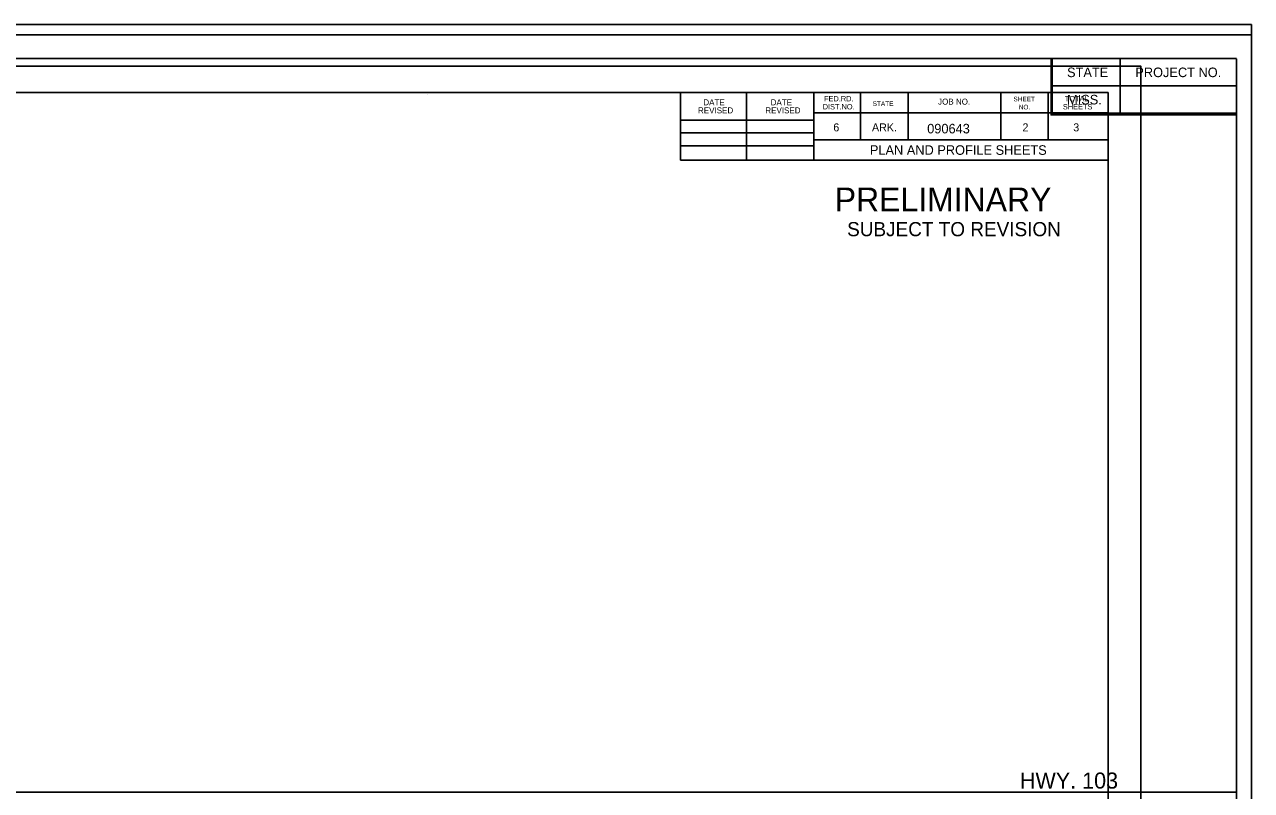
# Model space of a CAD drawing. Extents: x 1383694 to 1386843, y 1973227 to 1975727.
# Drawn here: x 1385944 to 1386843, y 1974979 to 1975540 of the extents above; entities that cross this region are included whole.
import ezdxf

# ---------------------------------------------------------------- set-up
doc = ezdxf.new("R2010")
doc.units = 0
for name, color, linetype in [('R_Border', 7, 'Continuous'), ('R_Border Prem', 7, 'Continuous'), ('R_No Plot', 7, 'Continuous'), ('SHEET_BORDER', 7, 'Continuous'), ('SHEET_BORDER_TX', 7, 'Continuous'), ('SHEET_PLOTTING_SHAPE', 7, 'Continuous')]:
    doc.layers.add(name, color=color, linetype=linetype)

msp = doc.modelspace()

# ---------------------------------------------------------------- linework, layer by layer
at = {"layer": 'R_Border'}
for p, q in [((1385156.93, 1975490.04), (1386737.83, 1975490.04)), ((1386239.07, 1975488.74), (1386239.07, 1975488.74)), ((1386239.07, 1975488.74), (1386239.07, 1975488.74)), ((1386424.63, 1975440.64), (1386424.63, 1975490.04)), ((1386473.03, 1975440.64), (1386473.03, 1975490.04)), ((1386522.33, 1975490.04), (1386522.33, 1975440.64)), ((1386556.53, 1975490.04), (1386556.53, 1975455.34)), ((1386591.23, 1975490.04), (1386591.23, 1975455.34)), ((1386659.13, 1975490.04), (1386659.13, 1975455.34)), ((1386693.83, 1975490.04), (1386693.83, 1975455.34)), ((1386737.83, 1974462.74), (1386737.83, 1975490.04)), ((1386737.83, 1975475.34), (1386522.33, 1975475.34)), ((1386424.63, 1975469.94), (1386522.33, 1975469.94)), ((1386424.63, 1975460.64), (1386522.33, 1975460.64)), ((1386737.83, 1975455.34), (1386522.33, 1975455.34)), ((1386537.13, 1975455.34), (1386737.83, 1975455.34)), ((1386424.63, 1975450.94), (1386522.33, 1975450.94)), ((1386737.83, 1975440.64), (1386424.63, 1975440.64))]:
    msp.add_line(p, q, dxfattribs=at)
at = {"layer": 'R_No Plot'}
msp.add_line((1385094.96, 1975509.53), (1386761.63, 1975509.53), dxfattribs=at)
msp.add_lwpolyline([(1385094.93, 1975509.53), (1386761.63, 1975509.53), (1386761.63, 1974442.85), (1385094.93, 1974442.85)], close=True, dxfattribs=at)
at = {"layer": 'SHEET_BORDER'}
for p, q in [((1386842.73, 1975539.94), (1386842.73, 1975539.94)), ((1385082.73, 1975532.44), (1386842.73, 1975532.44)), ((1385156.73, 1975514.94), (1386831.73, 1975514.94)), ((1386831.73, 1975514.89), (1386831.73, 1974464.94))]:
    msp.add_line(p, q, dxfattribs=at)
msp.add_lwpolyline([(1385156.73, 1975514.94), (1385156.73, 1974977.44), (1386831.73, 1974977.44), (1386831.73, 1975473.74), (1386695.93, 1975473.74), (1386695.93, 1975514.94)], close=True, dxfattribs=at)
at = {"layer": 'SHEET_BORDER_TX'}
for p, q in [((1386696.68, 1975514.89), (1386696.68, 1975474.89)), ((1386746.68, 1975514.89), (1386746.68, 1975474.89)), ((1386831.68, 1975494.89), (1386696.68, 1975494.89)), ((1386696.68, 1975474.89), (1386831.68, 1975474.89))]:
    msp.add_line(p, q, dxfattribs=at)
at = {"layer": 'SHEET_PLOTTING_SHAPE'}
msp.add_lwpolyline([(1385112.73, 1974439.94), (1386842.73, 1974439.94), (1386842.73, 1975539.94), (1385112.73, 1975539.94)], close=True, dxfattribs=at)

# ---------------------------------------------------------------- texts
at = {"layer": 'R_Border'}
for s, height, p in [('DATE', 4.396, (1386441.32, 1975480.72)), ('DATE', 4.396, (1386490.62, 1975480.72)), ('DIST.NO.', 3.91, (1386528.73, 1975477.74)), ('FED.RD.', 3.91, (1386529.73, 1975483.64)), ('STATE', 3.42, (1386565.33, 1975480.24)), ('JOB NO.', 4.396, (1386613.23, 1975481.24)), ('SHEET', 3.42, (1386668.43, 1975483.64)), ('SHEETS', 3.91, (1386704.63, 1975477.74)), ('TOTAL', 3.91, (1386706.03, 1975483.64)), ('REVISED', 4.396, (1386437.42, 1975474.82)), ('REVISED', 4.396, (1386486.72, 1975474.82)), ('NO.', 3.42, (1386672.33, 1975477.74)), ('6', 5.86, (1386536.53, 1975461.64)), ('ARK.', 5.861, (1386564.83, 1975461.64)), ('090643', 7, (1386605.26, 1975460.15)), ('2', 5.86, (1386675.05, 1975461.64)), ('3', 5.86, (1386712.23, 1975461.64)), ('PLAN AND PROFILE SHEETS', 7, (1386563.28, 1975444.46)), ('HWY. 103', 11.79, (1386673.19, 1974980.03))]:
    msp.add_text(s, height=height, dxfattribs=at).set_placement(p)
at = {"layer": 'R_Border Prem'}
for s, height, p in [('PRELIMINARY', 17.5, (1386537.59, 1975402.96)), ('SUBJECT TO REVISION', 10.3756, (1386546.64, 1975384.81))]:
    msp.add_text(s, height=height, dxfattribs=at).set_placement(p)
at = {"layer": 'SHEET_BORDER_TX'}
for s, height, p in [('STATE', 7, (1386707.68, 1975501.39)), ('PROJECT NO.', 6.9999, (1386757.68, 1975501.39)), ('MISS.', 7, (1386707.68, 1975481.39))]:
    msp.add_text(s, height=height, dxfattribs=at).set_placement(p)

doc.saveas('drawing.dxf')
